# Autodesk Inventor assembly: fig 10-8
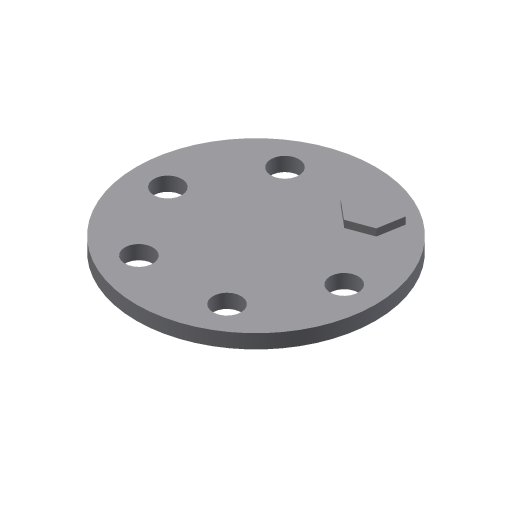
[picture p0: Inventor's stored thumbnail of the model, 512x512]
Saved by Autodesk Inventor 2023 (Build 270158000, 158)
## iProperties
Created: 2008-05
Part Number: fig 10-8
Document SubType Name: Assembly
Designer: CADCIM
Author: CADCIM
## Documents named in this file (3)
- D:\PROJECTS\Project 2022\Autodesk Inventor For Professional 2023\RESOURCES INVENTOR 2023\RESOURCES INVENTOR 2023\Inventor_2023_Part\Inventor_2023_Part\c10_Inv_2023_prt\fig 10-8.iam
- D:\PROJECTS\Project 2022\Autodesk Inventor For Professional 2023\RESOURCES INVENTOR 2023\RESOURCES INVENTOR 2023\Inventor_2023_Part\Inventor_2023_Part\c10_Inv_2023_prt\Part4.ipt
- D:\PROJECTS\Project 2022\Autodesk Inventor For Professional 2023\RESOURCES INVENTOR 2023\RESOURCES INVENTOR 2023\Inventor_2023_Part\Inventor_2023_Part\c10_Inv_2023_prt\Part5.ipt
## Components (2 placed, 2 different names)
1. Part4:1 — Insert:1
2. Part5:1 — Insert:1
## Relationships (1: Insert 1)
- Insert:1: Part4:1 ↔ Part5:1
